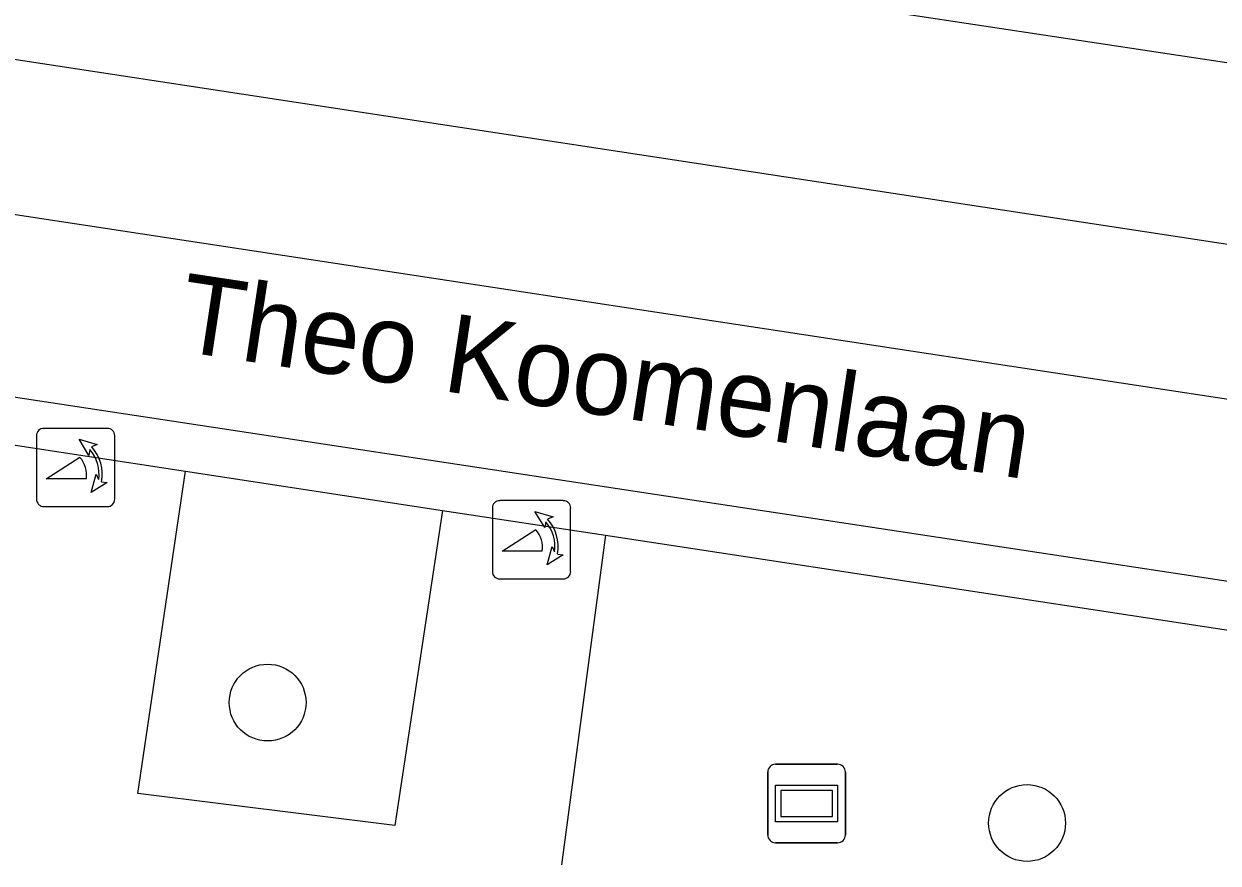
# Model space of a CAD drawing. Extents: x 161094 to 161705, y 379509 to 380907.
# Drawn here: x 161555.75 to 161570.96, y 380431.93 to 380442.62 of the extents above; entities that cross this region are included whole.
import ezdxf

# ---------------------------------------------------------------- set-up
doc = ezdxf.new("R2010")
doc.units = 0
for name, color, linetype in [('IMGEO_Boom', 7, 'Continuous'), ('IMGEO_Openbare_ruimte_label', 7, 'Continuous'), ('IMGEO_Poller', 7, 'Continuous'), ('IMGEO_Rijbaan_lokaal_gesloten', 7, 'Continuous'), ('IMGEO_Rijbaan_lokaal_open', 7, 'Continuous'), ('IMGEO_Verklikker', 7, 'Continuous'), ('IMGEO_Voetpad_open', 7, 'Continuous')]:
    doc.layers.add(name, color=color, linetype=linetype)

msp = doc.modelspace()

# ---------------------------------------------------------------- linework, layer by layer
at = {"layer": 'IMGEO_Boom'}
for centre in [(161558.855, 380433.974), (161568.524, 380432.44)]:
    msp.add_circle(centre, 0.489, dxfattribs=at)
at = {"layer": 'IMGEO_Poller'}
for p, q in [((161556.814, 380437.467), (161556.006, 380437.467)), ((161556.814, 380437.467), (161556.006, 380437.467)), ((161555.912, 380437.372), (161555.912, 380436.565)), ((161555.912, 380437.372), (161555.912, 380436.565)), ((161556.908, 380436.565), (161556.908, 380437.372)), ((161556.908, 380436.565), (161556.908, 380437.372)), ((161562.619, 380436.546), (161561.811, 380436.546)), ((161562.619, 380436.546), (161561.811, 380436.546)), ((161556.006, 380436.47), (161556.814, 380436.47)), ((161556.006, 380436.47), (161556.814, 380436.47)), ((161561.717, 380436.451), (161561.717, 380435.644)), ((161561.717, 380436.451), (161561.717, 380435.644)), ((161562.713, 380435.644), (161562.713, 380436.451)), ((161562.713, 380435.644), (161562.713, 380436.451)), ((161561.811, 380435.549), (161562.619, 380435.549)), ((161561.811, 380435.549), (161562.619, 380435.549))]:
    msp.add_line(p, q, dxfattribs=at)
for points in [[(161556.591, 380437.196), (161556.579, 380437.123), (161556.454, 380437.328)], [(161556.454, 380437.328), (161556.685, 380437.262), (161556.614, 380437.23)], [(161556.547, 380436.823), (161556.034, 380436.823), (161556.464, 380437.098)], [(161556.607, 380436.651), (161556.673, 380436.882), (161556.703, 380436.814)], [(161556.739, 380436.787), (161556.811, 380436.776), (161556.607, 380436.651)], [(161562.396, 380436.275), (161562.384, 380436.202), (161562.259, 380436.407)], [(161562.259, 380436.407), (161562.49, 380436.341), (161562.419, 380436.309)], [(161562.352, 380435.902), (161561.839, 380435.902), (161562.269, 380436.177)], [(161562.412, 380435.73), (161562.478, 380435.961), (161562.508, 380435.893)], [(161562.544, 380435.866), (161562.616, 380435.855), (161562.412, 380435.73)]]:
    msp.add_lwpolyline(points, dxfattribs=at)
for centre, radius, start, end in [((161556.006, 380437.372), 0.0946, 90, 180), ((161556.006, 380437.372), 0.0946, 90, 180), ((161556.814, 380437.372), 0.0946, 0, 90), ((161556.814, 380437.372), 0.0946, 0, 90), ((161556.233, 380436.883), 0.476, 351.7527, 41.1691), ((161556.233, 380436.883), 0.516, 349.3569, 42.2912), ((161556.219, 380436.873), 0.332, 351.3247, 42.4854), ((161556.006, 380436.565), 0.0946, 180, 270), ((161556.006, 380436.565), 0.0946, 180, 270), ((161556.814, 380436.565), 0.0946, 270, 0), ((161556.814, 380436.565), 0.0946, 270, 0), ((161561.811, 380436.451), 0.0946, 90, 180), ((161561.811, 380436.451), 0.0946, 90, 180), ((161562.619, 380436.451), 0.0946, 0, 90), ((161562.619, 380436.451), 0.0946, 0, 90), ((161562.038, 380435.962), 0.476, 351.7527, 41.1691), ((161562.038, 380435.962), 0.516, 349.3569, 42.2912), ((161562.024, 380435.952), 0.332, 351.3247, 42.4854), ((161561.811, 380435.644), 0.0946, 180, 270), ((161561.811, 380435.644), 0.0946, 180, 270), ((161562.619, 380435.644), 0.0946, 270, 0), ((161562.619, 380435.644), 0.0946, 270, 0)]:
    msp.add_arc(centre, radius, start, end, dxfattribs=at)
at = {"layer": 'IMGEO_Rijbaan_lokaal_gesloten'}
for points in [[(161586.07, 380439.832), (161585.979, 380439.898), (161581.527, 380440.544), (161556.757, 380444.287), (161512, 380451.031)], [(161585.474, 380435.644), (161504.655, 380447.955), (161504.951, 380449.901), (161585.752, 380437.576)], [(161509.279, 380444.908), (161585.149, 380433.385)]]:
    msp.add_lwpolyline(points, dxfattribs=at)
at = {"layer": 'IMGEO_Rijbaan_lokaal_open'}
for points in [[(161550.751, 380437.998), (161557.811, 380436.921)], [(161557.811, 380436.921), (161561.082, 380436.422)], [(161561.082, 380436.422), (161563.155, 380436.106)], [(161563.155, 380436.106), (161582.946, 380433.087)]]:
    msp.add_lwpolyline(points, dxfattribs=at)
at = {"layer": 'IMGEO_Verklikker'}
for p, q in [((161565.322, 380433.189), (161566.112, 380433.189)), ((161566.112, 380433.189), (161565.322, 380433.189)), ((161565.222, 380432.289), (161565.222, 380433.089)), ((161565.222, 380433.089), (161565.222, 380432.289)), ((161566.212, 380433.089), (161566.212, 380432.289)), ((161566.212, 380432.289), (161566.212, 380433.089)), ((161566.112, 380432.189), (161565.322, 380432.189)), ((161565.322, 380432.189), (161566.112, 380432.189))]:
    msp.add_line(p, q, dxfattribs=at)
for points in [[(161565.323, 380432.921), (161566.111, 380432.921), (161566.111, 380432.457), (161565.323, 380432.457), (161565.323, 380432.921)], [(161565.388, 380432.856), (161565.388, 380432.522), (161566.046, 380432.522), (161566.046, 380432.856), (161565.388, 380432.856)]]:
    msp.add_lwpolyline(points, dxfattribs=at)
for centre, start, end in [((161565.322, 380433.089), 90, 180), ((161565.322, 380433.089), 90, 180), ((161566.112, 380433.089), 0, 90), ((161566.112, 380433.089), 360, 90), ((161565.322, 380432.289), 180, 270), ((161565.322, 380432.289), 180, 270), ((161566.112, 380432.289), 270, 0), ((161566.112, 380432.289), 270, 0)]:
    msp.add_arc(centre, 0.1, start, end, dxfattribs=at)
at = {"layer": 'IMGEO_Voetpad_open'}
for points in [[(161561.082, 380436.422), (161560.473, 380432.408), (161557.203, 380432.816), (161557.811, 380436.921)], [(161563.155, 380436.106), (161562.595, 380431.908)]]:
    msp.add_lwpolyline(points, dxfattribs=at)

# ---------------------------------------------------------------- texts
at = {"layer": 'IMGEO_Openbare_ruimte_label'}
msp.add_text('Theo Koomenlaan', height=1, rotation=351.3758, dxfattribs=at).set_placement((161557.682, 380438.459))

doc.saveas('drawing.dxf')
